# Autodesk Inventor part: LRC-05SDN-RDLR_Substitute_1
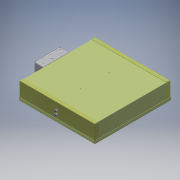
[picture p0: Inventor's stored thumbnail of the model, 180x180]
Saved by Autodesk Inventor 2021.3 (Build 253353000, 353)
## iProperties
Part Number: LRC-05SDN-RDLR_Substitute_1
Material: Generic
Document SubType Name: Modeling
Designer: JChurch
Manufacturer: Standard
Standards Organization: Custom
Density: 1 g/cm^3
Appearance: Smooth - Black
Author: JChurch
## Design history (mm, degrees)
derived "LRC-05SDN-RDLR.iam"
body "Solid9"
node "830399-00-00.ipt:1"
node "885000-00-00.iam:1::830000-00-00.ipt:1"
body "Solid10"
node "885000-00-00.iam:1::509424-00-00.ipt:1"
body "Solid11"
node "885000-00-00.iam:1::830593-00-00.ipt:1"
body "Solid12"
node "885000-00-00.iam:1::506002-00-00.ipt:1"
body "Solid13"
node "885000-00-00.iam:1::506002-00-00.ipt:2"
body "Solid14"
node "885000-00-00.iam:1::506002-00-00.ipt:3"
body "Solid15"
node "885000-00-00.iam:1::506002-00-00.ipt:4"
body "Solid16"
node "885000-00-00.iam:1::506002-00-00.ipt:5"
body "Solid17"
node "885000-00-00.iam:1::506002-00-00.ipt:6"
body "Solid18"
node "885000-00-00.iam:1::506002-00-00.ipt:7"
body "Solid19"
node "885000-00-00.iam:1::506002-00-00.ipt:8"
body "Solid20"
node "885000-00-00.iam:1::506002-00-00.ipt:9"
body "Solid21"
node "885000-00-00.iam:1::506002-00-00.ipt:10"
body "Solid22"
node "885000-00-00.iam:1::506002-00-00.ipt:11"
body "Solid23"
node "885000-00-00.iam:1::506002-00-00.ipt:12"
body "Solid24"
node "885000-00-00.iam:1::506002-00-00.ipt:13"
body "Solid25"
node "885000-00-00.iam:1::506002-00-00.ipt:14"
body "Solid26"
node "885000-00-00.iam:1::500027-00-00.ipt:1"
body "Solid27"
node "885000-00-00.iam:1::500027-00-00.ipt:2"
body "Solid28"
node "885000-00-00.iam:1::502116-00-00.ipt:1"
body "Solid29"
node "885000-00-00.iam:1::502116-00-00.ipt:2"
body "Solid30"
node "885000-00-00.iam:1::501030-00-00.ipt:1"
body "Solid31"
node "885000-00-00.iam:1::501030-00-00.ipt:2"
body "Solid32"
node "885000-00-00.iam:1::501030-00-00.ipt:3"
body "Solid33"
node "885000-00-00.iam:1::501030-00-00.ipt:4"
body "Solid34"
node "885000-00-00.iam:1::500027-00-00.ipt:3"
body "Solid35"
node "885000-00-00.iam:1::500027-00-00.ipt:4"
body "Solid36"
node "885000-00-00.iam:1::501030-00-00.ipt:5"
body "Solid37"
node "885000-00-00.iam:1::500027-00-00.ipt:5"
body "Solid38"
node "885000-00-00.iam:1::501030-00-00.ipt:6"
body "Solid39"
node "885000-00-00.iam:1::500027-00-00.ipt:6"
body "Solid40"
node "885000-00-00.iam:1::830593-00-00.ipt:2"
body "Solid41"
node "885000-00-00.iam:1::507032-00-00.ipt:1"
body "Solid42"
node "885000-00-00.iam:1::640042-00-03.ipt:1"
body "Solid43"
node "885000-00-00.iam:1::501030-00-00.ipt:9"
body "Solid44"
node "885000-00-00.iam:1::501030-00-00.ipt:10"
body "Solid45"
node "885000-00-00.iam:1::501030-00-00.ipt:11"
body "Solid46"
node "885000-00-00.iam:1::501030-00-00.ipt:12"
body "Solid47"
node "885000-00-00.iam:1::503031-00-00.ipt:1"
body "Solid48"
node "885000-00-00.iam:1::503031-00-00.ipt:2"
body "Solid49"
node "885000-00-00.iam:1::509425-00-00.ipt:1"
body "Solid50"
node "750905-XX-YY.iam:1::710109-00-31.ipt:1"
body "Solid51"
node "750905-XX-YY.iam:1::507075-00-38.ipt:1"
body "Solid52"
node "750905-XX-YY.iam:1::507075-00-38.ipt:2"
body "Solid53"
node "750905-XX-YY.iam:1::510052-00-00.ipt:1"
body "Solid54"
node "725075-02-00.ipt:1"
body "Solid55"
other parameters: "d15" = 61.595, "d16" = 9.525, "d17" = 9.525, "d35" = 5.08
